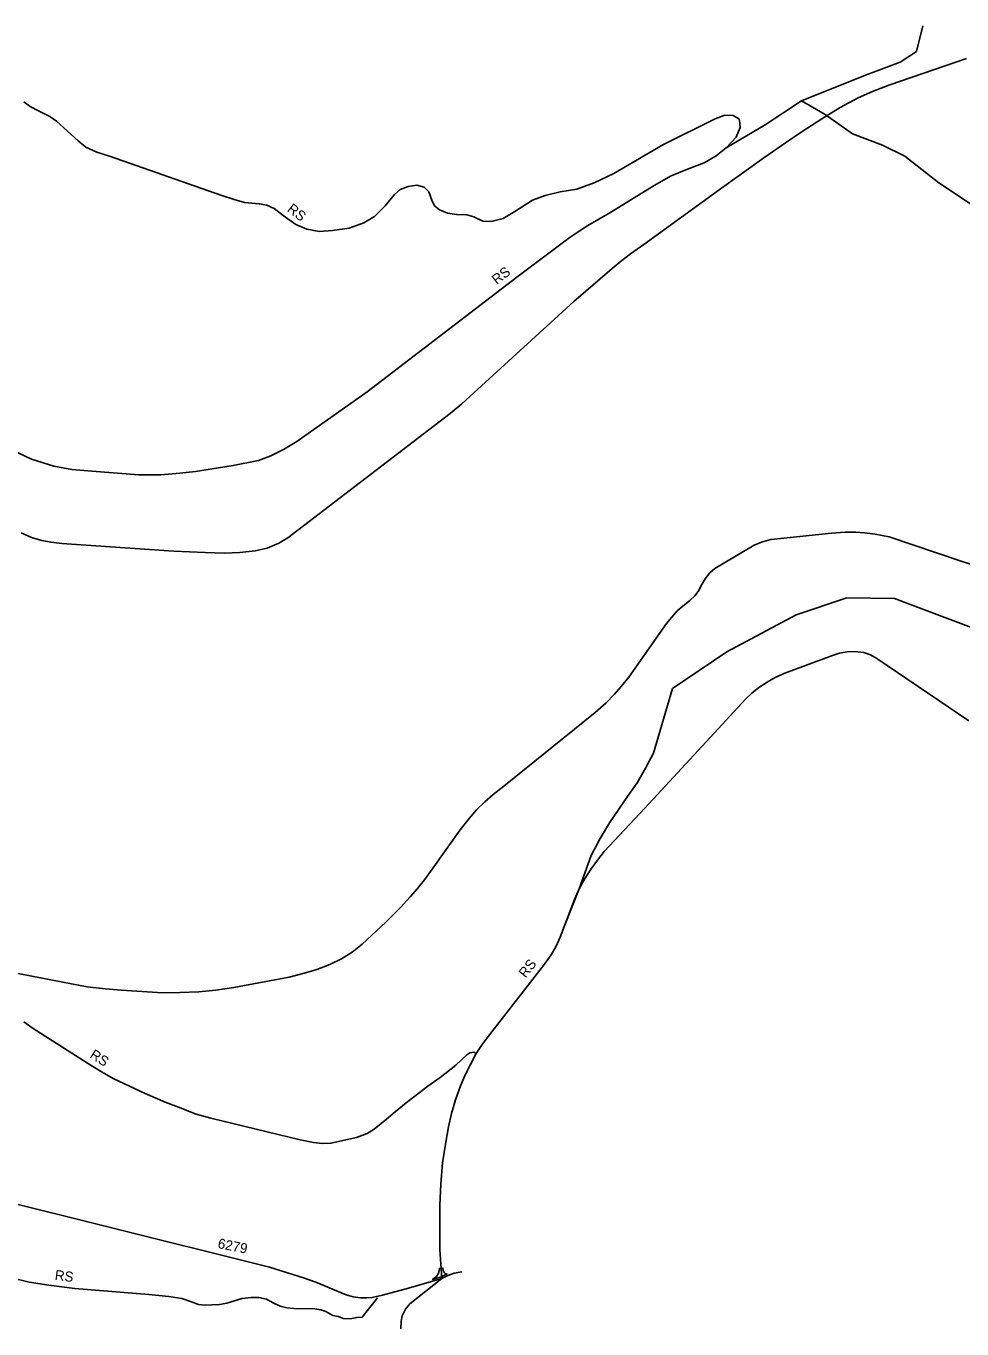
# Model space of a CAD drawing. Extents: x -546703 to -534152, y -1046534 to -1035676.
# Drawn here: x -545182 to -544245, y -1045805 to -1044501 of the extents above; entities that cross this region are included whole.
import ezdxf

# ---------------------------------------------------------------- set-up
doc = ezdxf.new("R2010")
doc.units = 0
doc.layers.add('Vrstva 11', color=7, linetype='Continuous')
doc.layers.add('Vrstva 22', color=7, linetype='Continuous')

msp = doc.modelspace()

# ---------------------------------------------------------------- linework, layer by layer
at = {"layer": 'Vrstva 11'}
for points in [[(-545186.7, -1045008.5), (-545176.2, -1045013), (-545165.7, -1045016.2), (-545156.6, -1045017.8), (-545145.7, -1045019.2), (-545033.7, -1045026.7), (-545002.4, -1045028.1), (-544983.2, -1045028.7), (-544967.9, -1045028.1), (-544952.4, -1045026.5), (-544940.5, -1045023.7), (-544928.9, -1045018.8), (-544919.7, -1045013.4), (-544909.6, -1045005.7), (-544757.2, -1044889), (-544745.5, -1044879.3), (-544733.6, -1044868.4), (-544633.6, -1044777.1), (-544595.3, -1044743.9), (-544585.4, -1044735.9), (-544576.9, -1044729.4), (-544563.6, -1044719.9), (-544488.3, -1044665.2), (-544443.5, -1044633.3), (-544421.9, -1044618.1), (-544405, -1044606.8), (-544385.6, -1044594.3), (-544367, -1044583), (-544349.1, -1044573.3), (-544334.9, -1044566.8), (-544317.4, -1044560.2), (-544240.7, -1044533.7)], [(-545208.9, -1045445.5), (-545136.2, -1045459.8), (-545120.5, -1045462.5), (-545102.3, -1045464.7), (-545086.5, -1045465.9), (-545044.8, -1045468.5), (-545027.9, -1045468.4), (-545008.8, -1045467.7), (-544991.7, -1045466), (-544973.9, -1045463.2), (-544918.4, -1045453), (-544902.2, -1045448.7), (-544890.7, -1045445.2), (-544877.7, -1045440.2), (-544866.2, -1045434.5), (-544855.5, -1045427.8), (-544845.5, -1045420), (-544821.6, -1045398.1), (-544806.9, -1045383.4), (-544797.3, -1045372.7), (-544789.9, -1045364.4), (-544783.1, -1045355.7), (-544775.4, -1045345), (-544747.2, -1045305.6), (-544738.4, -1045294.3), (-544730.9, -1045285.6), (-544722.7, -1045277.4), (-544714.2, -1045270.1), (-544703.7, -1045261.9), (-544612.1, -1045188.3), (-544601.3, -1045178.6), (-544592.8, -1045169.8), (-544586.1, -1045162.3), (-544578.4, -1045152.8), (-544547.3, -1045108), (-544540.9, -1045099.2), (-544535.4, -1045092.7), (-544530.1, -1045086.3), (-544517.4, -1045076.2), (-544512.1, -1045071), (-544508.7, -1045066.5), (-544505.4, -1045060), (-544502.2, -1045054.3), (-544497.5, -1045048.3), (-544492.5, -1045044), (-544453.2, -1045020.6), (-544445.7, -1045017.6), (-544436.5, -1045015.1), (-544423.5, -1045013.6), (-544375.8, -1045008.6), (-544362.1, -1045007.7), (-544351.3, -1045007.9), (-544342.9, -1045008.4), (-544332.1, -1045009.6), (-544318.1, -1045012.4), (-544246.9, -1045036.3), (-544179.8, -1045058.1)], [(-544765.8, -1045754.6), (-544767.5, -1045725.4), (-544767.8, -1045699), (-544767.5, -1045681.1), (-544766.7, -1045660), (-544764.9, -1045638.6), (-544761.7, -1045618.1), (-544759.1, -1045602.7), (-544756.1, -1045589.2), (-544752.1, -1045575.8), (-544747, -1045561.7), (-544742, -1045549.9), (-544737, -1045540.2), (-544731.2, -1045529.4), (-544724.5, -1045519.2), (-544718.1, -1045510.5), (-544662.9, -1045440.1), (-544656.3, -1045430.5), (-544651.3, -1045421.8), (-544647.2, -1045412.9), (-544642.8, -1045401.6), (-544633, -1045375.2), (-544628.4, -1045364.7), (-544623, -1045354.9), (-544616.4, -1045344.6), (-544609.9, -1045336), (-544603.2, -1045327.2), (-544562.5, -1045284), (-544497.2, -1045213.3), (-544461.4, -1045174.5), (-544455.5, -1045168.8), (-544448.4, -1045163), (-544440.3, -1045157.7), (-544432.1, -1045153), (-544422.4, -1045148.9), (-544374.9, -1045131), (-544367.8, -1045128.9), (-544360.2, -1045127.5), (-544352.3, -1045127), (-544343.4, -1045128.1), (-544336.6, -1045130.6), (-544330.5, -1045134), (-544238.5, -1045196.6)], [(-545206.8, -1045676), (-545101, -1045702.4), (-544938.2, -1045743.2), (-544904.2, -1045753.7), (-544891.8, -1045758.2), (-544861.3, -1045770.8), (-544854.2, -1045772.8), (-544847, -1045773.7), (-544840.6, -1045773.7), (-544835.5, -1045773.4), (-544824.9, -1045771), (-544799, -1045764.2), (-544765.8, -1045754.6)], [(-544806.7, -1045804.9), (-544806.4, -1045797.1), (-544805.2, -1045791.8), (-544801.9, -1045785), (-544797.6, -1045779.8), (-544765.8, -1045754.6), (-544759.7, -1045751.5), (-544753.2, -1045749.2), (-544745.5, -1045747.8)]]:
    msp.add_lwpolyline(points, dxfattribs=at)
msp.add_lwpolyline([(-544760.4, -1045749.9), (-544762.2, -1045749.3), (-544763.3, -1045748.3), (-544764.3, -1045746.6), (-544764.6, -1045744), (-544768.1, -1045744.4), (-544768.5, -1045748.1), (-544769.5, -1045750.5), (-544771, -1045752.4), (-544774.9, -1045755.4), (-544766.2, -1045752.9)], close=True, dxfattribs=at)
at = {"layer": 'Vrstva 22'}
for points in [[(-544405.9, -1044576.3), (-544341.7, -1044550.5), (-544307, -1044537.6), (-544290.8, -1044526.7), (-544284.4, -1044501.3)], [(-545194.7, -1044926), (-545176.1, -1044934.6), (-545153.7, -1044941.7), (-545135.8, -1044944.9), (-545115.9, -1044946.8), (-545068.8, -1044950.3), (-545046.7, -1044950.3), (-545027.8, -1044948.7), (-545012.1, -1044947.1), (-544974.4, -1044941), (-544949.1, -1044936.2), (-544936.9, -1044931.4), (-544924.1, -1044925), (-544910.6, -1044917), (-544840.2, -1044867.3), (-544690.6, -1044752.6), (-544637.1, -1044712.5), (-544619.5, -1044701), (-544597.7, -1044688.2), (-544553.2, -1044660.9), (-544536.2, -1044651.3), (-544519.9, -1044644.6), (-544503.2, -1044638.2), (-544491.1, -1044631.1), (-544481.1, -1044623.1), (-544471.2, -1044612.5), (-544467, -1044602.9), (-544467.7, -1044595.6), (-544468.6, -1044594.3), (-544474.1, -1044590.8), (-544482.4, -1044590.4), (-544492.3, -1044594.3), (-544544.5, -1044620.2), (-544593.5, -1044648.8), (-544613.4, -1044658.4), (-544630.7, -1044664.5), (-544647.4, -1044667.3), (-544662.4, -1044670.9), (-544674.9, -1044675.7), (-544692.5, -1044686.9), (-544704.4, -1044693.9), (-544716.2, -1044696.8), (-544724.5, -1044696.5), (-544733.5, -1044692.3), (-544740.6, -1044690.4), (-544750.8, -1044690.1), (-544760.1, -1044688.5), (-544768.1, -1044685.3), (-544772.9, -1044681.1), (-544775.8, -1044675.7), (-544778.7, -1044667.3), (-544783.2, -1044662.5), (-544790.8, -1044660.6), (-544799.2, -1044661.9), (-544807.2, -1044664.8), (-544812.9, -1044669.9), (-544822.5, -1044681.1), (-544833.1, -1044692), (-544843.7, -1044698.4), (-544858.4, -1044703.6), (-544875.1, -1044706.1), (-544888.5, -1044706.8), (-544900.7, -1044704.5), (-544911.6, -1044700), (-544924.4, -1044691.1), (-544933.4, -1044684), (-544940.7, -1044680.5), (-544948.4, -1044679.2), (-544963.1, -1044677.9), (-544973.4, -1044675), (-544985.9, -1044670.9), (-545098, -1044631.5), (-545110.8, -1044627.6), (-545121.7, -1044622.5), (-545129.4, -1044616.4), (-545151.1, -1044596.5), (-545157.9, -1044592), (-545169.1, -1044586.3), (-545177.7, -1044581.8), (-545183.8, -1044577.3)], [(-544405.9, -1044576.3), (-544442.3, -1044600.3), (-544481.1, -1044623.1)], [(-544159.9, -1044710), (-544188.6, -1044705.2), (-544225.7, -1044686.6), (-544268.4, -1044658.4), (-544302.3, -1044631.7), (-544324.9, -1044620.5), (-544354.8, -1044609.2), (-544382.2, -1044589.8), (-544405.9, -1044576.3)], [(-544534.9, -1045164.1), (-544480.6, -1045127.5), (-544411.2, -1045090.4), (-544360.4, -1045073.4), (-544312.8, -1045074.2), (-544265.2, -1045092), (-544205.5, -1045114.6), (-544157.9, -1045133.9), (-544116, -1045147.6), (-544085.7, -1045148), (-544034.1, -1045138.4), (-543988.9, -1045116.6), (-543947, -1045081.1), (-543908.2, -1045031.9), (-543884.1, -1044951.2), (-543843.3, -1044834.6), (-543812.7, -1044783.8), (-543790.9, -1044752.3), (-543779.6, -1044722.5), (-543767.5, -1044687.8), (-543759.4, -1044657.2), (-543759.4, -1044643.4), (-543771.5, -1044635.4), (-543793.2, -1044624.2)], [(-545208.9, -1045445.5), (-545136.2, -1045459.8), (-545120.5, -1045462.5), (-545102.3, -1045464.7), (-545086.5, -1045465.9), (-545044.8, -1045468.5), (-545027.9, -1045468.4), (-545008.8, -1045467.7), (-544991.7, -1045466), (-544973.9, -1045463.2), (-544918.4, -1045453), (-544902.2, -1045448.7), (-544890.7, -1045445.2), (-544877.7, -1045440.2), (-544866.2, -1045434.5), (-544855.5, -1045427.8), (-544845.5, -1045420), (-544821.6, -1045398.1), (-544806.9, -1045383.4), (-544797.3, -1045372.7), (-544789.9, -1045364.4), (-544783.1, -1045355.7), (-544775.4, -1045345), (-544747.2, -1045305.6), (-544738.4, -1045294.3), (-544730.9, -1045285.6), (-544722.7, -1045277.4), (-544714.2, -1045270.1), (-544703.7, -1045261.9), (-544612.1, -1045188.3), (-544601.3, -1045178.6), (-544592.8, -1045169.8), (-544586.1, -1045162.3), (-544578.4, -1045152.8), (-544547.3, -1045108), (-544540.9, -1045099.2), (-544535.4, -1045092.7), (-544530.1, -1045086.3), (-544517.4, -1045076.2), (-544512.1, -1045071), (-544508.7, -1045066.5), (-544505.4, -1045060), (-544502.2, -1045054.3), (-544497.5, -1045048.3), (-544492.5, -1045044), (-544453.2, -1045020.6), (-544445.7, -1045017.6), (-544436.5, -1045015.1), (-544423.5, -1045013.6), (-544375.8, -1045008.6), (-544362.1, -1045007.7), (-544351.3, -1045007.9), (-544342.9, -1045008.4), (-544332.1, -1045009.6), (-544318.1, -1045012.4), (-544246.9, -1045036.3), (-544179.8, -1045058.1)], [(-544534.9, -1045164.1), (-544553.8, -1045228.8), (-544561.8, -1045243.9), (-544570.2, -1045258.6), (-544579.1, -1045271.1), (-544598, -1045298.4), (-544607.3, -1045314.4), (-544616.3, -1045331.4), (-544628.4, -1045364.7), (-544642.8, -1045401.6), (-544647.2, -1045412.9), (-544651.3, -1045421.8), (-544656.3, -1045430.5), (-544662.9, -1045440.1), (-544718.1, -1045510.5), (-544724.5, -1045519.2), (-544731.2, -1045529.4)], [(-544765.8, -1045754.6), (-544767.5, -1045725.4), (-544767.8, -1045699), (-544767.5, -1045681.1), (-544766.7, -1045660), (-544764.9, -1045638.6), (-544761.7, -1045618.1), (-544759.1, -1045602.7), (-544756.1, -1045589.2), (-544752.1, -1045575.8), (-544747, -1045561.7), (-544742, -1045549.9), (-544731.2, -1045529.4), (-544733.6, -1045528), (-544737.8, -1045528.7), (-544740.7, -1045530.6), (-544751.7, -1045540.9), (-544767.3, -1045553.4), (-544779.5, -1045562.1), (-544801.2, -1045578.6), (-544812.5, -1045587.8), (-544821, -1045595.1), (-544833.2, -1045605), (-544840.3, -1045609.5), (-544851.1, -1045613.3), (-544876.6, -1045619.2), (-544885.1, -1045619.4), (-544894, -1045618.5), (-544907.4, -1045615.6), (-544996.7, -1045594.2), (-545011.5, -1045590), (-545029, -1045583.1), (-545042.4, -1045577.9), (-545062.4, -1045569.2), (-545093.7, -1045554.6), (-545103.9, -1045548.9), (-545116.4, -1045541.4), (-545174.5, -1045504.2), (-545184, -1045497.6)], [(-545206.8, -1045676), (-545101, -1045702.4), (-544938.2, -1045743.2), (-544904.2, -1045753.7), (-544891.8, -1045758.2), (-544861.3, -1045770.8), (-544854.2, -1045772.8), (-544847, -1045773.7), (-544840.6, -1045773.7), (-544835.5, -1045773.4), (-544824.9, -1045771), (-544799, -1045764.2), (-544765.8, -1045754.6)], [(-544806.7, -1045804.9), (-544806.4, -1045797.1), (-544805.2, -1045791.8), (-544801.9, -1045785), (-544797.6, -1045779.8), (-544765.8, -1045754.6), (-544759.7, -1045751.5), (-544753.2, -1045749.2), (-544745.5, -1045747.8)], [(-545197.4, -1045753.5), (-545178.5, -1045758), (-545159, -1045761.1), (-545132.8, -1045764.4), (-545058.9, -1045770.5), (-545038.9, -1045772.6), (-545025.7, -1045774.5), (-545016, -1045777.8), (-545009, -1045780.4), (-545002.4, -1045781.1), (-544995.8, -1045780.9), (-544988.2, -1045780.6), (-544980.7, -1045779), (-544965.4, -1045774.3), (-544956.4, -1045773.3), (-544948.9, -1045773.3), (-544941.1, -1045775.2), (-544934.3, -1045778.7), (-544927.5, -1045782), (-544920.6, -1045783.9), (-544913.6, -1045784.6), (-544892.6, -1045784.9), (-544886.7, -1045785.8), (-544881.8, -1045787.5), (-544874.7, -1045791.5), (-544869.2, -1045792.6), (-544864.5, -1045794.3), (-544857.5, -1045794.7), (-544850.8, -1045793.4), (-544845.3, -1045793), (-544830.1, -1045773.8)]]:
    msp.add_lwpolyline(points, dxfattribs=at)

# ---------------------------------------------------------------- texts
for s, rotation, p in [('RS', 321.8259, (-544921.1, -1044686)), ('RS', 37.4904, (-544710.8, -1044760.5)), ('RS', 51.8974, (-544681.8, -1045454.4)), ('RS', 327.3782, (-545118.6, -1045532.9)), ('6279', 348.7738, (-544990.4, -1045723.9)), ('RS', 352.8072, (-545153.3, -1045755.7))]:
    msp.add_text(s, height=10, rotation=rotation, dxfattribs=at).set_placement(p)

doc.saveas('drawing.dxf')
